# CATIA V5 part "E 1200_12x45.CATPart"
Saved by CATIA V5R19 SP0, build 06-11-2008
Definition: E 1200_12x45
Nomenclature: E 1200_12x45
Description: PART--DESC
Material "Steel": density 7860 kg/m3, Young's modulus 2e+11 Pa, Poisson ratio 0.266, thermal expansion 1.17e-05 1/K
Bounding box of the stored display mesh (mm): x -254 to -236, y -184 to -166, z -273 to -216
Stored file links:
  G:\UTB\Kombinované\Bakalářská práce\Catia\FORMA\E 1200_12x45.CATPart
  D:\Aplikace\CATIA\Nová složka\win_b64\startup\materials\Catalog.CATMaterial
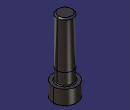
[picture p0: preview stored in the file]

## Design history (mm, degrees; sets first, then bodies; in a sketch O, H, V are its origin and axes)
Body1 "E 1200_12x45" (main body)
  Solid1: solid without history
